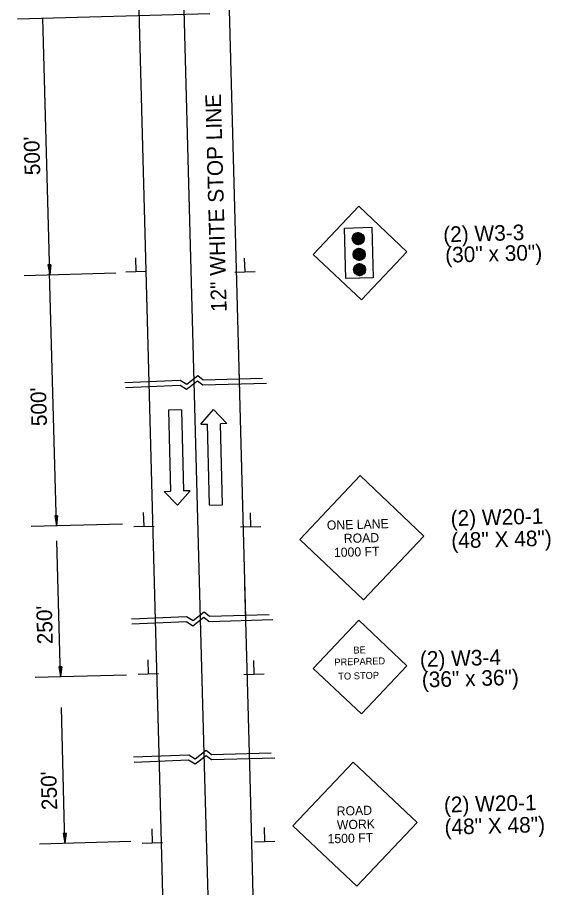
# Model space of a CAD drawing. Extents: x 1926836 to 1933254, y 596317 to 604524.
# Drawn here: x 1930880 to 1931090, y 598532.1 to 598874.9 of the extents above; entities that cross this region are included whole.
import ezdxf

# ---------------------------------------------------------------- set-up
doc = ezdxf.new("R2010")
doc.units = 0
doc.layers.add('Default', color=7, linetype='Continuous')
doc.layers.add('R_MOT', color=7, linetype='Continuous')

msp = doc.modelspace()

# ---------------------------------------------------------------- linework, layer by layer
at = {"layer": 'Default'}
for p, q in [((1930932.01, 598726.01), (1930927.62, 598889.59)), ((1930949.8, 598726.49), (1930945.4, 598890.07)), ((1930967.58, 598726.97), (1930963.19, 598890.55)), ((1930880.01, 598874.39), (1930955.85, 598876.43)), ((1930892.74, 598773.55), (1930890.03, 598874.65)), ((1931014.45, 598800.49), (1930996.52, 598781.52)), ((1931033.43, 598782.58), (1931014.45, 598800.49)), ((1931011.88, 598787.71), (1931014.17, 598790.12)), ((1931011.89, 598787.57), (1931014.31, 598790.13)), ((1931011.89, 598787.87), (1931014.01, 598790.11)), ((1931011.9, 598787.43), (1931014.45, 598790.12)), ((1931011.9, 598788.03), (1931013.85, 598790.09)), ((1931011.92, 598787.3), (1931014.58, 598790.11)), ((1931011.93, 598788.22), (1931013.67, 598790.05)), ((1931011.95, 598787.18), (1931014.7, 598790.09)), ((1931011.98, 598787.06), (1931014.82, 598790.06)), ((1931011.98, 598788.42), (1931013.47, 598789.99)), ((1931012.02, 598786.95), (1931014.93, 598790.03)), ((1931012.06, 598786.84), (1931015.04, 598790)), ((1931012.07, 598788.66), (1931013.23, 598789.89)), ((1931012.1, 598786.74), (1931015.15, 598789.96)), ((1931012.15, 598786.64), (1931015.25, 598789.91)), ((1931012.2, 598786.55), (1931015.35, 598789.87)), ((1931012.23, 598788.99), (1931012.91, 598789.71)), ((1931012.26, 598786.46), (1931015.44, 598789.81)), ((1931012.32, 598786.37), (1931015.53, 598789.76)), ((1931012.38, 598786.28), (1931015.62, 598789.7)), ((1931012.45, 598786.2), (1931015.71, 598789.64)), ((1931012.52, 598786.12), (1931015.79, 598789.58)), ((1931012.59, 598786.05), (1931015.87, 598789.51)), ((1931012.66, 598785.98), (1931015.94, 598789.44)), ((1931012.74, 598785.91), (1931016.01, 598789.36)), ((1931012.82, 598785.85), (1931016.08, 598789.28)), ((1931012.91, 598785.78), (1931016.15, 598789.2)), ((1931013, 598785.73), (1931016.21, 598789.12)), ((1931013.09, 598785.67), (1931016.27, 598789.03)), ((1931013.18, 598785.62), (1931016.33, 598788.94)), ((1931013.28, 598785.57), (1931016.38, 598788.84)), ((1931013.38, 598785.53), (1931016.43, 598788.74)), ((1931013.49, 598785.49), (1931016.47, 598788.64)), ((1931013.6, 598785.46), (1931016.51, 598788.53)), ((1931013.71, 598785.43), (1931016.55, 598788.42)), ((1931013.83, 598785.4), (1931016.58, 598788.3)), ((1931013.95, 598785.38), (1931016.61, 598788.18)), ((1931014.08, 598785.37), (1931016.63, 598788.05)), ((1931014.22, 598785.36), (1931016.64, 598787.92)), ((1931014.36, 598785.36), (1931016.65, 598787.77)), ((1931014.52, 598785.37), (1931016.64, 598787.62)), ((1931014.68, 598785.4), (1931016.63, 598787.45)), ((1931014.86, 598785.44), (1931016.6, 598787.27)), ((1931015.06, 598785.5), (1931016.55, 598787.07)), ((1931015.3, 598785.6), (1931016.46, 598786.82)), ((1931015.62, 598785.78), (1931016.3, 598786.5)), ((1931015.5, 598763.59), (1930996.52, 598781.52)), ((1931012.27, 598781.37), (1931014.7, 598783.93)), ((1931012.27, 598781.52), (1931014.55, 598783.93)), ((1931012.27, 598781.67), (1931014.4, 598783.92)), ((1931012.28, 598781.84), (1931014.23, 598783.89)), ((1931012.29, 598781.24), (1931014.83, 598783.92)), ((1931012.31, 598781.11), (1931014.96, 598783.91)), ((1931012.31, 598782.02), (1931014.05, 598783.85)), ((1931012.33, 598780.99), (1931015.09, 598783.89)), ((1931012.36, 598782.22), (1931013.85, 598783.79)), ((1931012.37, 598780.87), (1931015.2, 598783.86)), ((1931012.4, 598780.76), (1931015.32, 598783.83)), ((1931012.44, 598780.65), (1931015.43, 598783.8)), ((1931012.45, 598782.46), (1931013.62, 598783.69)), ((1931012.49, 598780.55), (1931015.53, 598783.76)), ((1931012.54, 598780.45), (1931015.64, 598783.72)), ((1931012.59, 598780.35), (1931015.73, 598783.67)), ((1931012.62, 598782.79), (1931013.3, 598783.51)), ((1931012.64, 598780.26), (1931015.83, 598783.62)), ((1931012.7, 598780.17), (1931015.92, 598783.56)), ((1931012.77, 598780.09), (1931016.01, 598783.51)), ((1931012.83, 598780.01), (1931016.09, 598783.44)), ((1931012.9, 598779.93), (1931016.17, 598783.38)), ((1931012.97, 598779.85), (1931016.25, 598783.31)), ((1931013.05, 598779.78), (1931016.33, 598783.24)), ((1931013.13, 598779.71), (1931016.4, 598783.17)), ((1931013.21, 598779.65), (1931016.47, 598783.09)), ((1931013.29, 598779.59), (1931016.53, 598783.01)), ((1931013.38, 598779.53), (1931016.6, 598782.92)), ((1931013.47, 598779.48), (1931016.65, 598782.83)), ((1931013.57, 598779.43), (1931016.71, 598782.74)), ((1931013.66, 598779.38), (1931016.76, 598782.65)), ((1931013.77, 598779.33), (1931016.81, 598782.55)), ((1931013.87, 598779.3), (1931016.86, 598782.44)), ((1931013.98, 598779.26), (1931016.9, 598782.34)), ((1931014.1, 598779.23), (1931016.93, 598782.23)), ((1931014.21, 598779.2), (1931016.97, 598782.11)), ((1931014.34, 598779.19), (1931016.99, 598781.98)), ((1931014.47, 598779.17), (1931017.01, 598781.86)), ((1931014.6, 598779.17), (1931017.03, 598781.72)), ((1931014.75, 598779.17), (1931017.03, 598781.58)), ((1931033.43, 598782.58), (1931015.5, 598763.59)), ((1930926.76, 598774.77), (1930926.61, 598780.24)), ((1930969.67, 598774.63), (1930969.52, 598780.1)), ((1931014.9, 598779.18), (1931017.03, 598781.42)), ((1931015.07, 598779.2), (1931017.01, 598781.26)), ((1931015.25, 598779.24), (1931016.98, 598781.07)), ((1931015.45, 598779.3), (1931016.93, 598780.87)), ((1931015.69, 598779.4), (1931016.85, 598780.63)), ((1931016, 598779.59), (1931016.68, 598780.3)), ((1930893.21, 598777.4), (1930892.06, 598777.37)), ((1930892.06, 598777.37), (1930892.74, 598773.55)), ((1930892.16, 598777.37), (1930892.72, 598774.19)), ((1930892.26, 598777.38), (1930892.71, 598774.85)), ((1930892.35, 598777.38), (1930892.69, 598775.49)), ((1930892.45, 598777.38), (1930892.67, 598776.14)), ((1930892.55, 598777.39), (1930892.66, 598776.78)), ((1930892.73, 598777.39), (1930892.66, 598776.78)), ((1930892.82, 598777.39), (1930892.67, 598776.14)), ((1930892.92, 598777.4), (1930892.69, 598775.49)), ((1930893.02, 598777.4), (1930892.71, 598774.85)), ((1930893.12, 598777.4), (1930892.72, 598774.19)), ((1930893.21, 598777.4), (1930892.74, 598773.55)), ((1930930.74, 598774.76), (1930922.74, 598774.55)), ((1930973.65, 598774.62), (1930965.65, 598774.41)), ((1931012.43, 598775.43), (1931014.78, 598777.91)), ((1931012.43, 598775.58), (1931014.63, 598777.9)), ((1931012.44, 598775.29), (1931014.92, 598777.9)), ((1931012.44, 598775.74), (1931014.47, 598777.88)), ((1931012.46, 598775.16), (1931015.05, 598777.89)), ((1931012.46, 598775.91), (1931014.3, 598777.85)), ((1931012.48, 598775.03), (1931015.18, 598777.88)), ((1931012.5, 598776.11), (1931014.11, 598777.8)), ((1931012.51, 598774.91), (1931015.3, 598777.86)), ((1931012.54, 598774.8), (1931015.42, 598777.83)), ((1931012.57, 598776.33), (1931013.89, 598777.72)), ((1931012.58, 598774.68), (1931015.53, 598777.8)), ((1931012.62, 598774.58), (1931015.64, 598777.76)), ((1931012.67, 598774.48), (1931015.74, 598777.72)), ((1931012.69, 598776.6), (1931013.62, 598777.59)), ((1931012.72, 598774.38), (1931015.84, 598777.67)), ((1931012.77, 598774.29), (1931015.94, 598777.62)), ((1931012.83, 598774.2), (1931016.03, 598777.57)), ((1931012.89, 598774.11), (1931016.12, 598777.52)), ((1931012.96, 598774.03), (1931016.21, 598777.46)), ((1931013.02, 598773.95), (1931016.29, 598777.39)), ((1931013.09, 598773.87), (1931016.37, 598777.33)), ((1931013.17, 598773.8), (1931016.45, 598777.26)), ((1931013.24, 598773.73), (1931016.52, 598777.18)), ((1931013.32, 598773.66), (1931016.59, 598777.11)), ((1931013.41, 598773.6), (1931016.66, 598777.03)), ((1931013.49, 598773.54), (1931016.72, 598776.95)), ((1931013.58, 598773.48), (1931016.78, 598776.86)), ((1931013.68, 598773.43), (1931016.84, 598776.77)), ((1931013.77, 598773.38), (1931016.9, 598776.68)), ((1931013.87, 598773.33), (1931016.95, 598776.58)), ((1931014.08, 598773.26), (1931017.04, 598776.37)), ((1931014.19, 598773.22), (1931017.08, 598776.26)), ((1931014.31, 598773.19), (1931017.11, 598776.15)), ((1931014.43, 598773.17), (1931017.14, 598776.03)), ((1931014.56, 598773.15), (1931017.16, 598775.91)), ((1931014.69, 598773.14), (1931017.18, 598775.77)), ((1931014.83, 598773.14), (1931017.19, 598775.63)), ((1931014.98, 598773.15), (1931017.19, 598775.49)), ((1931015.14, 598773.16), (1931017.19, 598775.33)), ((1931015.31, 598773.19), (1931017.17, 598775.15)), ((1931015.5, 598773.24), (1931017.13, 598774.96)), ((1931015.71, 598773.32), (1931017.06, 598774.75)), ((1930882.73, 598773.28), (1930918.74, 598774.25)), ((1930895.4, 598674.69), (1930892.72, 598774.41)), ((1931015.97, 598773.44), (1931016.95, 598774.48)), ((1931016.43, 598773.77), (1931016.65, 598774)), ((1930969.96, 598638.38), (1930967.33, 598736.35)), ((1930934.39, 598637.43), (1930932.01, 598726.01)), ((1930952.17, 598637.9), (1930949.8, 598726.49)), ((1931014.99, 598694.38), (1930991.2, 598669.27)), ((1931040.1, 598670.58), (1931014.99, 598694.38)), ((1930929.89, 598674.4), (1930929.74, 598679.86)), ((1930971.93, 598674.24), (1930971.78, 598679.7)), ((1930885.38, 598674.42), (1930921.4, 598675.39)), ((1930895.87, 598678.54), (1930894.72, 598678.51)), ((1930894.72, 598678.51), (1930895.4, 598674.69)), ((1930894.81, 598678.51), (1930895.38, 598675.33)), ((1930894.91, 598678.51), (1930895.36, 598675.99)), ((1930895.01, 598678.52), (1930895.34, 598676.63)), ((1930895.1, 598678.52), (1930895.33, 598677.28)), ((1930895.2, 598678.52), (1930895.31, 598677.92)), ((1930895.38, 598678.53), (1930895.31, 598677.92)), ((1930895.48, 598678.53), (1930895.33, 598677.28)), ((1930895.58, 598678.53), (1930895.34, 598676.63)), ((1930895.67, 598678.53), (1930895.36, 598675.99)), ((1930895.77, 598678.54), (1930895.38, 598675.33)), ((1930895.87, 598678.54), (1930895.4, 598674.69)), ((1930933.87, 598674.39), (1930925.87, 598674.17)), ((1930975.91, 598674.23), (1930967.91, 598674.01)), ((1930896.99, 598615.26), (1930895.56, 598668.64)), ((1931016.3, 598645.49), (1930991.2, 598669.27)), ((1931040.1, 598670.58), (1931016.3, 598645.49)), ((1930971.65, 598575.45), (1930969.6, 598651.49)), ((1930953.85, 598575.32), (1930952.17, 598637.9)), ((1930936.06, 598575.19), (1930934.39, 598637.43)), ((1931014.47, 598637.38), (1930996.54, 598618.41)), ((1931033.45, 598619.47), (1931014.47, 598637.38)), ((1930931.66, 598616.3), (1930931.52, 598621.77)), ((1930973.27, 598616.13), (1930973.13, 598621.59)), ((1930897.46, 598619.11), (1930896.31, 598619.08)), ((1930896.31, 598619.08), (1930896.99, 598615.26)), ((1930896.41, 598619.08), (1930896.97, 598615.9)), ((1930896.51, 598619.08), (1930896.96, 598616.56)), ((1930896.6, 598619.08), (1930896.94, 598617.19)), ((1930896.7, 598619.09), (1930896.92, 598617.84)), ((1930896.8, 598619.09), (1930896.9, 598618.49)), ((1930896.98, 598619.09), (1930896.9, 598618.49)), ((1930897.07, 598619.1), (1930896.92, 598617.84)), ((1930897.17, 598619.1), (1930896.94, 598617.19)), ((1930897.27, 598619.1), (1930896.96, 598616.56)), ((1930897.37, 598619.1), (1930896.97, 598615.9)), ((1930897.46, 598619.11), (1930896.99, 598615.26)), ((1931015.53, 598600.49), (1930996.54, 598618.41)), ((1931033.45, 598619.47), (1931015.53, 598600.49)), ((1930886.98, 598614.99), (1930922.99, 598615.95)), ((1930935.65, 598616.29), (1930927.64, 598616.08)), ((1930977.26, 598616.12), (1930969.25, 598615.9)), ((1930898.75, 598549.63), (1930897.32, 598603.01)), ((1931012.33, 598581.55), (1930988.54, 598556.45)), ((1931037.44, 598557.76), (1931012.33, 598581.55)), ((1930937.76, 598511.79), (1930936.06, 598575.19)), ((1930955.53, 598512.74), (1930953.85, 598575.32)), ((1930973.3, 598513.69), (1930971.65, 598575.45)), ((1930933.21, 598549.74), (1930933.06, 598555.2)), ((1930977.48, 598550.23), (1930977.33, 598555.7)), ((1931013.65, 598532.67), (1930988.54, 598556.45)), ((1931037.44, 598557.76), (1931013.65, 598532.67)), ((1930899.23, 598553.48), (1930898.07, 598553.45)), ((1930898.07, 598553.45), (1930898.75, 598549.63)), ((1930898.17, 598553.45), (1930898.74, 598550.27)), ((1930898.27, 598553.45), (1930898.72, 598550.93)), ((1930898.36, 598553.45), (1930898.7, 598551.57)), ((1930898.46, 598553.46), (1930898.68, 598552.22)), ((1930898.56, 598553.46), (1930898.67, 598552.86)), ((1930898.74, 598553.46), (1930898.67, 598552.86)), ((1930898.84, 598553.47), (1930898.68, 598552.22)), ((1930898.94, 598553.47), (1930898.7, 598551.57)), ((1930899.03, 598553.47), (1930898.72, 598550.93)), ((1930899.13, 598553.47), (1930898.74, 598550.27)), ((1930899.23, 598553.48), (1930898.75, 598549.63)), ((1930888.74, 598549.36), (1930924.75, 598550.32)), ((1930937.19, 598549.73), (1930929.19, 598549.51)), ((1930981.46, 598550.22), (1930973.46, 598550.01))]:
    msp.add_line(p, q, dxfattribs=at)
msp.add_lwpolyline([(1931008.82, 598791.93), (1931019.59, 598792.22), (1931020.12, 598772.36), (1931009.36, 598772.07)], close=True, dxfattribs=at)
for points in [[(1930922.39, 598731.12), (1930944.18, 598732.03), (1930946.69, 598730.44), (1930951.03, 598733.79), (1930953.12, 598732.14), (1930976.62, 598732.77)], [(1930922.64, 598729.08), (1930944.15, 598729.99), (1930946.66, 598728.39), (1930951, 598731.75), (1930953.09, 598730.1), (1930978.11, 598730.76)], [(1930924.89, 598637.99), (1930946.68, 598638.9), (1930949.19, 598637.31), (1930953.53, 598640.66), (1930955.62, 598639.01), (1930979.12, 598639.64)], [(1930925.14, 598635.95), (1930946.65, 598636.86), (1930949.16, 598635.26), (1930953.5, 598638.62), (1930955.59, 598636.97), (1930980.61, 598637.63)], [(1930925.71, 598583.53), (1930947.49, 598584.44), (1930950.01, 598582.85), (1930954.35, 598586.2), (1930956.44, 598584.55), (1930979.93, 598585.18)], [(1930925.96, 598581.49), (1930947.46, 598582.4), (1930949.98, 598580.8), (1930954.32, 598584.16), (1930956.41, 598582.51), (1930981.43, 598583.18)]]:
    msp.add_lwpolyline(points, dxfattribs=at)
for centre in [(1931014.27, 598787.74), (1931014.65, 598781.55), (1931014.81, 598775.52)]:
    msp.add_circle(centre, 2.38, dxfattribs=at)
at = {"layer": 'R_MOT'}
for p, q in [((1930944.64, 598720.29), (1930939.52, 598720.15)), ((1930939.52, 598720.15), (1930940.38, 598688.22)), ((1930944.64, 598720.29), (1930945.49, 598688.35)), ((1930952.29, 598714.62), (1930957.26, 598720.37)), ((1930957.26, 598720.37), (1930962.52, 598714.9)), ((1930952.29, 598714.62), (1930954.85, 598714.69)), ((1930955.71, 598682.75), (1930954.85, 598714.69)), ((1930962.52, 598714.9), (1930959.96, 598714.83)), ((1930960.82, 598682.89), (1930959.96, 598714.83)), ((1930937.82, 598688.15), (1930940.38, 598688.22)), ((1930943.09, 598682.68), (1930937.82, 598688.15)), ((1930948.05, 598688.42), (1930943.09, 598682.68)), ((1930948.05, 598688.42), (1930945.49, 598688.35)), ((1930955.71, 598682.75), (1930960.82, 598682.89))]:
    msp.add_line(p, q, dxfattribs=at)

# ---------------------------------------------------------------- texts
at = {"layer": 'Default'}
for s, height, rotation, p in [('12" WHITE STOP LINE', 6.1396, 91.5377, (1930962.46, 598758.93)), ("500'", 6.14, 91.5377, (1930889.02, 598812.8)), ('(2) W3-3', 6.14, 1.5377, (1931047.83, 598786.33)), ('(30" x 30")', 6.1396, 1.5377, (1931048.6, 598778.27)), ("500'", 6.14, 91.5377, (1930891.67, 598713.93)), ('(2) W20-1', 6.14, 1.5377, (1931050.76, 598674.47)), ('ONE LANE', 3.603, 1.5381, (1931001.95, 598673.04)), ('ROAD', 3.602, 1.5377, (1931008.63, 598667.82)), ('(48" X 48")', 6.1396, 1.5377, (1931050.99, 598665.71)), ('1000 FT', 3.604, 1.5383, (1931004.74, 598662.3)), ("250'", 6.14, 91.5377, (1930893.98, 598628.01)), ('BE', 2.72, 1.6381, (1931012.41, 598624.26)), ('(2) W3-4', 6.14, 1.5377, (1931038.63, 598618.99)), ('PREPARED', 2.719, 1.638, (1931004.91, 598619.51)), ('TO STOP', 2.737, 1.5383, (1931006.44, 598613.95)), ('(36" x 36")', 6.1396, 1.5377, (1931039.39, 598610.92)), ("250'", 6.14, 91.5377, (1930895.73, 598562.7)), ('(2) W20-1', 6.14, 1.5377, (1931048.1, 598561.64)), ('ROAD', 3.603, 1.5381, (1931005.83, 598560.4)), ('WORK', 3.602, 1.5377, (1931005.91, 598554.99)), ('(48" X 48")', 6.1396, 1.5377, (1931048.34, 598552.88)), ('1500 FT', 3.604, 1.5383, (1931002.23, 598549.49))]:
    msp.add_text(s, height=height, rotation=rotation, dxfattribs=at).set_placement(p)

doc.saveas('drawing.dxf')
